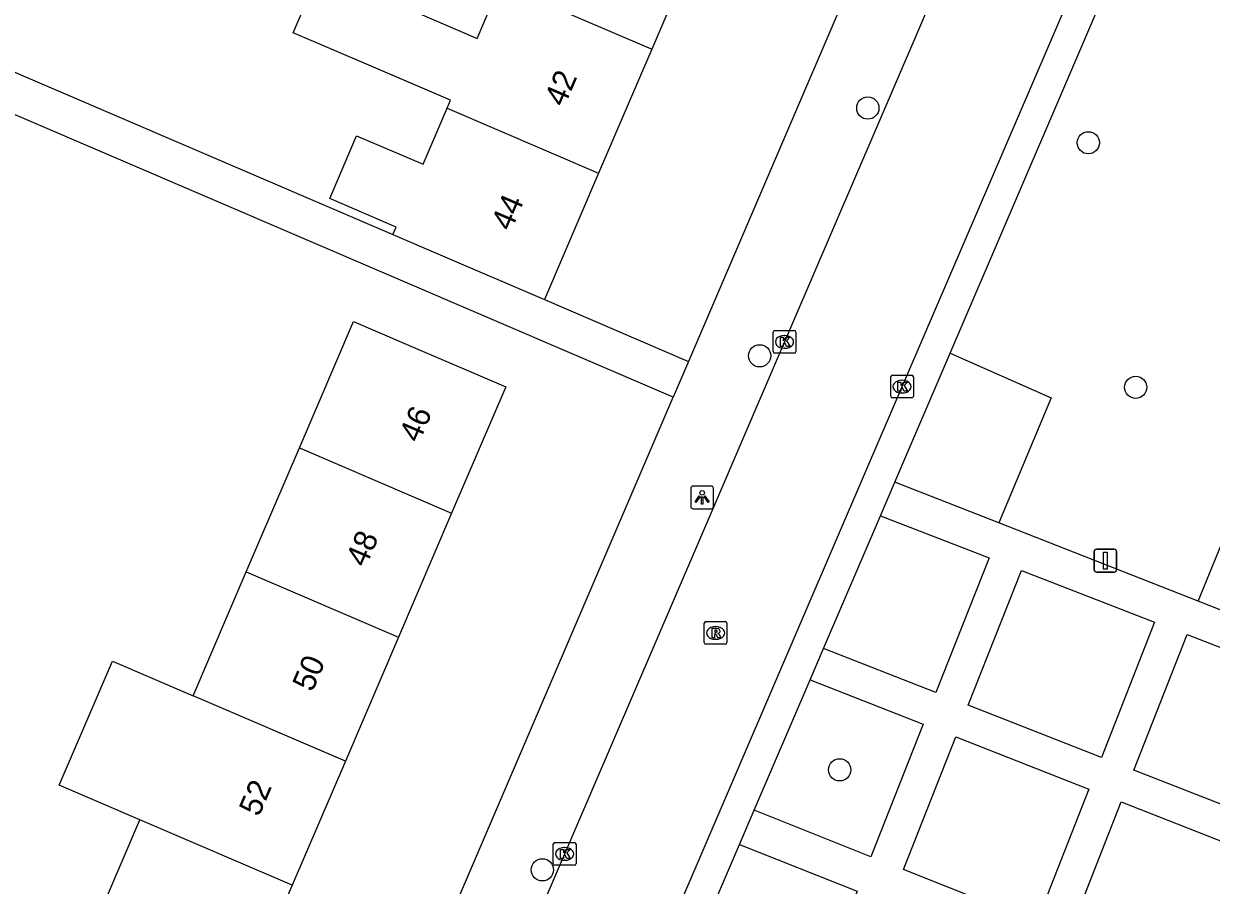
# Model space of a CAD drawing. Extents: x 159822 to 160765, y 380693 to 381634.
# Drawn here: x 160233.8 to 160286.1, y 381284.5 to 381322.4 of the extents above; entities that cross this region are included whole.
import ezdxf

# ---------------------------------------------------------------- set-up
doc = ezdxf.new("R2010")
doc.units = 0
for name, color, linetype in [('IMGEO_Boom', 7, 'Continuous'), ('IMGEO_Groenvoorziening', 7, 'Continuous'), ('IMGEO_Kolk', 7, 'Continuous'), ('IMGEO_Lichtpunt', 7, 'Continuous'), ('IMGEO_Pand', 7, 'Continuous'), ('IMGEO_Pand_nummerreeks', 7, 'Continuous'), ('IMGEO_Rijbaan_lokaal_open', 7, 'Continuous'), ('IMGEO_Rioolput', 7, 'Continuous'), ('IMGEO_Verkeersbordpaal', 7, 'Continuous'), ('IMGEO_Voetpad_halfverhard', 7, 'Continuous'), ('IMGEO_Voetpad_open', 7, 'Continuous')]:
    doc.layers.add(name, color=color, linetype=linetype)

msp = doc.modelspace()

# ---------------------------------------------------------------- linework, layer by layer
at = {"layer": 'IMGEO_Boom'}
for centre in [(160271.006, 381318.7), (160280.714, 381317.174), (160266.243, 381307.8), (160282.805, 381306.415), (160269.766, 381289.579), (160256.675, 381285.178)]:
    msp.add_circle(centre, 0.489, dxfattribs=at)
at = {"layer": 'IMGEO_Groenvoorziening'}
for points in [[(160274.636, 381307.919), (160279.077, 381305.951), (160276.769, 381300.449)], [(160285.55, 381296.997), (160287.869, 381302.661), (160293.501, 381300.328), (160291.365, 381294.711)]]:
    msp.add_lwpolyline(points, dxfattribs=at)
at = {"layer": 'IMGEO_Kolk'}
for p, q in [((160266.913, 381308.913), (160267.765, 381308.913)), ((160266.838, 381307.987), (160266.838, 381308.839)), ((160267.326, 381308.693), (160267.351, 381308.693)), ((160267.839, 381308.839), (160267.839, 381307.987)), ((160267.765, 381307.913), (160266.913, 381307.913)), ((160267.349, 381308.133), (160267.324, 381308.133)), ((160272.013, 381306.02), (160272.013, 381306.872)), ((160272.088, 381306.946), (160272.94, 381306.946)), ((160273.014, 381306.872), (160273.014, 381306.02)), ((160272.501, 381306.726), (160272.526, 381306.726)), ((160272.94, 381305.946), (160272.088, 381305.946)), ((160272.524, 381306.166), (160272.499, 381306.166)), ((160257.155, 381285.455), (160257.155, 381286.307)), ((160257.23, 381286.381), (160258.082, 381286.381)), ((160257.643, 381286.161), (160257.668, 381286.161)), ((160258.156, 381286.307), (160258.156, 381285.455)), ((160258.082, 381285.381), (160257.23, 381285.381)), ((160257.666, 381285.601), (160257.641, 381285.601))]:
    msp.add_line(p, q, dxfattribs=at)
for points in [[(160266.913, 381308.913), (160267.765, 381308.913)], [(160266.838, 381307.987), (160266.838, 381308.839)], [(160267.159, 381308.613), (160267.282, 381308.613), (160267.282, 381308.462), (160267.412, 381308.613), (160267.576, 381308.613), (160267.43, 381308.462), (160267.583, 381308.213), (160267.431, 381308.213), (160267.346, 381308.377), (160267.282, 381308.31), (160267.282, 381308.213), (160267.159, 381308.213), (160267.159, 381308.613)], [(160267.839, 381308.839), (160267.839, 381307.987)], [(160267.765, 381307.913), (160266.913, 381307.913)], [(160272.013, 381306.02), (160272.013, 381306.872)], [(160272.088, 381306.946), (160272.94, 381306.946)], [(160273.014, 381306.872), (160273.014, 381306.02)], [(160272.334, 381306.646), (160272.457, 381306.646), (160272.457, 381306.495), (160272.587, 381306.646), (160272.751, 381306.646), (160272.605, 381306.495), (160272.758, 381306.246), (160272.606, 381306.246), (160272.521, 381306.41), (160272.457, 381306.343), (160272.457, 381306.246), (160272.334, 381306.246), (160272.334, 381306.646)], [(160272.94, 381305.946), (160272.088, 381305.946)], [(160257.155, 381285.455), (160257.155, 381286.307)], [(160257.23, 381286.381), (160258.082, 381286.381)], [(160257.476, 381286.081), (160257.599, 381286.081), (160257.599, 381285.93), (160257.729, 381286.081), (160257.893, 381286.081), (160257.747, 381285.93), (160257.9, 381285.681), (160257.748, 381285.681), (160257.663, 381285.845), (160257.599, 381285.778), (160257.599, 381285.681), (160257.476, 381285.681), (160257.476, 381286.081)], [(160258.156, 381286.307), (160258.156, 381285.455)], [(160258.082, 381285.381), (160257.23, 381285.381)]]:
    msp.add_lwpolyline(points, dxfattribs=at)
for centre, start, end in [((160266.915, 381308.837), 91.552, 178.448), ((160266.915, 381308.837), 91.552, 178.448), ((160267.763, 381308.837), 1.552, 88.448), ((160267.763, 381308.837), 1.552, 88.448), ((160266.915, 381307.989), 181.552, 268.448), ((160266.915, 381307.989), 181.552, 268.448), ((160267.763, 381307.989), 271.552, 358.448), ((160267.763, 381307.989), 271.552, 358.448), ((160272.09, 381306.87), 91.552, 178.448), ((160272.09, 381306.87), 91.552, 178.448), ((160272.938, 381306.87), 1.552, 88.448), ((160272.938, 381306.87), 1.552, 88.448), ((160272.09, 381306.022), 181.552, 268.448), ((160272.09, 381306.022), 181.552, 268.448), ((160272.938, 381306.022), 271.552, 358.448), ((160272.938, 381306.022), 271.552, 358.448), ((160257.232, 381286.305), 91.552, 178.448), ((160257.232, 381286.305), 91.552, 178.448), ((160258.08, 381286.305), 1.552, 88.448), ((160258.08, 381286.305), 1.552, 88.448), ((160257.232, 381285.457), 181.552, 268.448), ((160257.232, 381285.457), 181.552, 268.448), ((160258.08, 381285.457), 271.552, 358.448), ((160258.08, 381285.457), 271.552, 358.448)]:
    msp.add_arc(centre, 0.0765, start, end, dxfattribs=at)
for centre, major_axis, ratio, start_param, end_param in [((160267.325, 381308.413), (-0.387, 0.002), 0.722429, 4.712389, 7.853982), ((160267.35, 381308.413), (-0.39, 0.002), 0.717154, 1.570796, 4.712389), ((160272.5, 381306.446), (-0.387, 0.002), 0.722429, 4.712389, 7.853982), ((160272.525, 381306.446), (-0.39, 0.002), 0.717154, 1.570796, 4.712389), ((160257.642, 381285.881), (-0.387, 0.002), 0.722429, 4.712389, 7.853982), ((160257.667, 381285.881), (-0.39, 0.002), 0.717154, 1.570796, 4.712389)]:
    msp.add_ellipse(centre, major_axis=major_axis, ratio=ratio, start_param=start_param, end_param=end_param, dxfattribs=at)
at = {"layer": 'IMGEO_Lichtpunt'}
for p, q in [((160263.211, 381301.972), (160263.211, 381301.165)), ((160263.211, 381301.972), (160263.211, 381301.165)), ((160264.113, 381302.067), (160263.305, 381302.067)), ((160264.113, 381302.067), (160263.305, 381302.067)), ((160264.207, 381301.165), (160264.207, 381301.972)), ((160264.207, 381301.165), (160264.207, 381301.972)), ((160263.305, 381301.071), (160264.113, 381301.071)), ((160263.305, 381301.071), (160264.113, 381301.071))]:
    msp.add_line(p, q, dxfattribs=at)
for points in [[(160263.585, 381301.636), (160263.624, 381301.608), (160263.436, 381301.346), (160263.398, 381301.373), (160263.585, 381301.636)], [(160263.687, 381301.588), (160263.734, 381301.588), (160263.734, 381301.266), (160263.687, 381301.266), (160263.687, 381301.588)], [(160263.797, 381301.608), (160263.835, 381301.635), (160264.022, 381301.373), (160263.983, 381301.345), (160263.797, 381301.608)]]:
    msp.add_lwpolyline(points, dxfattribs=at)
msp.add_circle((160263.71, 381301.77), 0.0994, dxfattribs=at)
for centre, start, end in [((160263.305, 381301.972), 90, 180), ((160263.305, 381301.972), 90, 180), ((160264.113, 381301.972), 0, 90), ((160264.113, 381301.972), 0, 90), ((160263.305, 381301.165), 180, 270), ((160263.305, 381301.165), 180, 270), ((160264.113, 381301.165), 270, 0), ((160264.113, 381301.165), 270, 360)]:
    msp.add_arc(centre, 0.0946, start, end, dxfattribs=at)
at = {"layer": 'IMGEO_Pand'}
for points in [[(160263.83, 381326.752), (160261.491, 381321.297)], [(160252.482, 381318.7), (160252.632, 381319.049), (160249.028, 381320.594), (160245.705, 381322.019), (160247.246, 381325.612), (160248.777, 381325.683), (160249.468, 381325.386), (160249.873, 381326.33), (160251.236, 381325.745), (160250.393, 381323.777), (160250.194, 381323.313), (160253.798, 381321.768), (160254.821, 381324.155)], [(160261.491, 381321.297), (160261.382, 381321.344), (160254.821, 381324.155)], [(160261.491, 381321.297), (160259.151, 381315.841)], [(160250.095, 381313.134), (160250.238, 381313.466), (160247.309, 381314.722), (160248.492, 381317.481), (160251.421, 381316.226), (160252.482, 381318.7)], [(160252.482, 381318.7), (160259.042, 381315.888), (160259.151, 381315.841)], [(160259.151, 381315.841), (160256.764, 381310.274)], [(160250.095, 381313.134), (160252.169, 381312.245), (160256.764, 381310.274)], [(160245.973, 381303.746), (160248.359, 381309.311), (160250.468, 381308.407), (160255.063, 381306.436), (160252.677, 381300.872)], [(160243.634, 381298.293), (160245.973, 381303.746)], [(160245.973, 381303.746), (160252.677, 381300.872)], [(160252.677, 381300.872), (160250.338, 381295.418)], [(160241.295, 381292.838), (160243.634, 381298.293)], [(160243.634, 381298.293), (160250.338, 381295.418)], [(160250.338, 381295.418), (160247.999, 381289.964)], [(160238.955, 381287.383), (160235.401, 381288.907), (160237.739, 381294.362), (160241.295, 381292.838)], [(160247.999, 381289.964), (160241.295, 381292.838)], [(160247.999, 381289.964), (160245.66, 381284.509)], [(160236.617, 381281.929), (160238.955, 381287.383)], [(160245.66, 381284.509), (160238.955, 381287.383)], [(160245.66, 381284.509), (160243.321, 381279.054)]]:
    msp.add_lwpolyline(points, dxfattribs=at)
at = {"layer": 'IMGEO_Rijbaan_lokaal_open'}
for points in [[(160253.445, 381276.078), (160264.367, 381301.496), (160265.868, 381304.988), (160276.881, 381330.602)], [(160281.951, 381328.405), (160270.908, 381302.714), (160258.532, 381273.892)]]:
    msp.add_lwpolyline(points, dxfattribs=at)
at = {"layer": 'IMGEO_Rioolput'}
for p, q in [((160263.803, 381295.178), (160263.803, 381296.03)), ((160263.878, 381296.104), (160264.73, 381296.104)), ((160264.291, 381295.884), (160264.316, 381295.884)), ((160264.804, 381296.03), (160264.804, 381295.178)), ((160264.314, 381295.324), (160264.289, 381295.324)), ((160264.73, 381295.104), (160263.878, 381295.104))]:
    msp.add_line(p, q, dxfattribs=at)
for points in [[(160263.803, 381295.178), (160263.803, 381296.03)], [(160263.878, 381296.104), (160264.73, 381296.104)], [(160264.804, 381296.03), (160264.804, 381295.178)], [(160264.392, 381295.802), (160264.14, 381295.804), (160264.14, 381295.404)], [(160264.14, 381295.404), (160264.264, 381295.404), (160264.264, 381295.566), (160264.275, 381295.566)], [(160264.318, 381295.723), (160264.264, 381295.723), (160264.264, 381295.642)], [(160264.264, 381295.642), (160264.316, 381295.642)], [(160264.322, 381295.537), (160264.393, 381295.404), (160264.533, 381295.404), (160264.468, 381295.53)], [(160264.73, 381295.104), (160263.878, 381295.104)]]:
    msp.add_lwpolyline(points, dxfattribs=at)
for centre, radius, start, end in [((160263.88, 381296.028), 0.0765, 91.552, 178.448), ((160263.88, 381296.028), 0.0765, 91.552, 178.448), ((160264.728, 381296.028), 0.0765, 1.552, 88.448), ((160264.728, 381296.028), 0.0765, 1.552, 88.448), ((160264.274, 381295.513), 0.0533, 26.0293, 88.6989), ((160264.3, 381295.831), 0.19, 274.7715, 282.9687), ((160264.324, 381295.627), 0.0964, 77.0061, 93.1865), ((160264.338, 381295.684), 0.0378, 276.6634, 79.6772), ((160264.391, 381295.692), 0.109, 350.3612, 89.416), ((160264.389, 381295.692), 0.112, 277.5842, 350.9817), ((160264.373, 381295.477), 0.108, 29.5134, 73.7905), ((160263.88, 381295.18), 0.0765, 181.552, 268.448), ((160263.88, 381295.18), 0.0765, 181.552, 268.448), ((160264.728, 381295.18), 0.0765, 271.552, 358.448), ((160264.728, 381295.18), 0.0765, 271.552, 358.448)]:
    msp.add_arc(centre, radius, start, end, dxfattribs=at)
for centre, major_axis, ratio, start_param, end_param in [((160264.29, 381295.604), (-0.387, 0.002), 0.722429, 4.712389, 7.853982), ((160264.315, 381295.604), (-0.39, 0.002), 0.717154, 1.570796, 4.712389)]:
    msp.add_ellipse(centre, major_axis=major_axis, ratio=ratio, start_param=start_param, end_param=end_param, dxfattribs=at)
at = {"layer": 'IMGEO_Verkeersbordpaal'}
for p, q in [((160280.972, 381298.384), (160280.972, 381299.184)), ((160280.972, 381299.184), (160280.972, 381298.384)), ((160281.072, 381299.284), (160281.862, 381299.284)), ((160281.862, 381299.284), (160281.072, 381299.284)), ((160281.962, 381299.184), (160281.962, 381298.384)), ((160281.962, 381298.384), (160281.962, 381299.184)), ((160281.862, 381298.284), (160281.072, 381298.284)), ((160281.072, 381298.284), (160281.862, 381298.284))]:
    msp.add_line(p, q, dxfattribs=at)
msp.add_lwpolyline([(160281.392, 381299.159), (160281.542, 381299.159), (160281.542, 381298.409), (160281.392, 381298.409), (160281.392, 381299.159)], dxfattribs=at)
for centre, start, end in [((160281.072, 381299.184), 90, 180), ((160281.072, 381299.184), 90, 180), ((160281.862, 381299.184), 0, 90), ((160281.862, 381299.184), 360, 90), ((160281.072, 381298.384), 180, 270), ((160281.072, 381298.384), 180, 270), ((160281.862, 381298.384), 270, 0), ((160281.862, 381298.384), 270, 0)]:
    msp.add_arc(centre, 0.1, start, end, dxfattribs=at)
at = {"layer": 'IMGEO_Voetpad_halfverhard'}
for points in [[(160228.154, 381327.509), (160226.205, 381323.374), (160250.095, 381313.134)], [(160262.44, 381305.973), (160225.471, 381321.826)], [(160256.764, 381310.274), (160263.116, 381307.549)]]:
    msp.add_lwpolyline(points, dxfattribs=at)
at = {"layer": 'IMGEO_Voetpad_open'}
for points in [[(160274.636, 381307.919), (160311.657, 381394.179)], [(160295.966, 381384.153), (160263.116, 381307.549)], [(160272.201, 381302.245), (160274.636, 381307.919)], [(160263.116, 381307.549), (160262.44, 381305.973)], [(160244.191, 381263.419), (160262.44, 381305.973)], [(160271.563, 381300.759), (160272.201, 381302.245)], [(160276.769, 381300.449), (160272.201, 381302.245)], [(160269.055, 381294.916), (160271.563, 381300.759)], [(160271.563, 381300.759), (160276.347, 381298.906), (160274.001, 381292.98), (160269.055, 381294.916)], [(160285.55, 381296.997), (160276.769, 381300.449)], [(160275.426, 381292.423), (160277.767, 381298.357), (160283.637, 381296.085), (160281.293, 381290.127), (160275.426, 381292.423)], [(160291.365, 381294.711), (160285.55, 381296.997)], [(160282.721, 381289.567), (160285.071, 381295.529), (160290.879, 381293.28), (160288.542, 381287.289), (160282.721, 381289.567)], [(160268.464, 381293.537), (160269.055, 381294.916)], [(160266.003, 381287.803), (160268.464, 381293.537)], [(160268.464, 381293.537), (160273.449, 381291.585), (160271.143, 381285.758), (160266.003, 381287.803)], [(160278.431, 381282.858), (160272.572, 381285.189), (160274.875, 381291.025), (160280.741, 381288.727), (160278.431, 381282.858)], [(160279.852, 381282.292), (160282.169, 381288.167), (160287.994, 381285.885), (160285.687, 381279.971), (160279.852, 381282.292)], [(160265.357, 381286.3), (160266.003, 381287.803)], [(160262.899, 381280.571), (160265.357, 381286.3)], [(160265.357, 381286.3), (160270.542, 381284.238), (160268.252, 381278.453), (160262.899, 381280.571)]]:
    msp.add_lwpolyline(points, dxfattribs=at)

# ---------------------------------------------------------------- texts
at = {"layer": 'IMGEO_Pand_nummerreeks'}
for s, rotation, p in [('42', 66.7897, (160257.64, 381318.712)), ('44', 66.7897, (160255.295, 381313.244)), ('46', 66.7886, (160251.245, 381303.929)), ('48', 66.7886, (160248.896, 381298.45)), ('50', 66.7886, (160246.546, 381292.968)), ('52', 66.7886, (160244.192, 381287.48))]:
    msp.add_text(s, height=1, rotation=rotation, dxfattribs=at).set_placement(p)

doc.saveas('drawing.dxf')
